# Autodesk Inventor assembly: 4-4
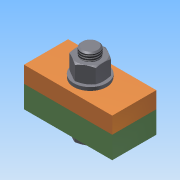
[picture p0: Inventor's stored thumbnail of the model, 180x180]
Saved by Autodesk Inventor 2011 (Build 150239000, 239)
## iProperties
Created: 2014-03
Part Number: 4-4
Document SubType Name: Assembly
Designer: Administrator
Author: Administrator
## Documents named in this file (6)
- C:\Documents and Settings\Administrator\桌面\模型\4-4.iam
- C:\Documents and Settings\Administrator\桌面\模型\4-4b.ipt
- C:\Documents and Settings\Administrator\桌面\模型\4-4a.ipt
- C:\Documents and Settings\Administrator\桌面\模型\4-4螺栓 GB_T 5782 M16 x 60.ipt
- C:\Documents and Settings\Administrator\桌面\模型\4-4螺母 GB_T 6170 M16.ipt
- C:\Documents and Settings\Administrator\桌面\模型\4-4平垫圈 GB_T 97.1 16.ipt
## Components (5 placed, 5 different names)
1. 4-4b:1 — 插入:1, 表面齐平:1, 插入:2
2. 4-4a:1 — 插入:1, 表面齐平:1, 插入:3
3. 4-4螺栓 GB_T 5782 M16 x 60:1 — 插入:2
4. 4-4螺母 GB_T 6170 M16:1 — 插入:4
5. 4-4平垫圈 GB_T 97.1 16:1 — 插入:3, 插入:4
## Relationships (5: Insert 4, Flush 1)
- 插入:1 [Insert]: 4-4b:1 ↔ 4-4a:1
- 表面齐平:1 [Flush]: 4-4b:1 ↔ 4-4a:1
- 插入:2 [Insert]: 4-4b:1 ↔ 4-4螺栓 GB_T 5782 M16 x 60:1
- 插入:3 [Insert]: 4-4a:1 ↔ 4-4平垫圈 GB_T 97.1 16:1
- 插入:4 [Insert]: 4-4螺母 GB_T 6170 M16:1 ↔ 4-4平垫圈 GB_T 97.1 16:1
